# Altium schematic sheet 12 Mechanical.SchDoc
size 420 x 297 mm; DocumentNumber: 12; SheetNumber: 12; SheetTotal: 12
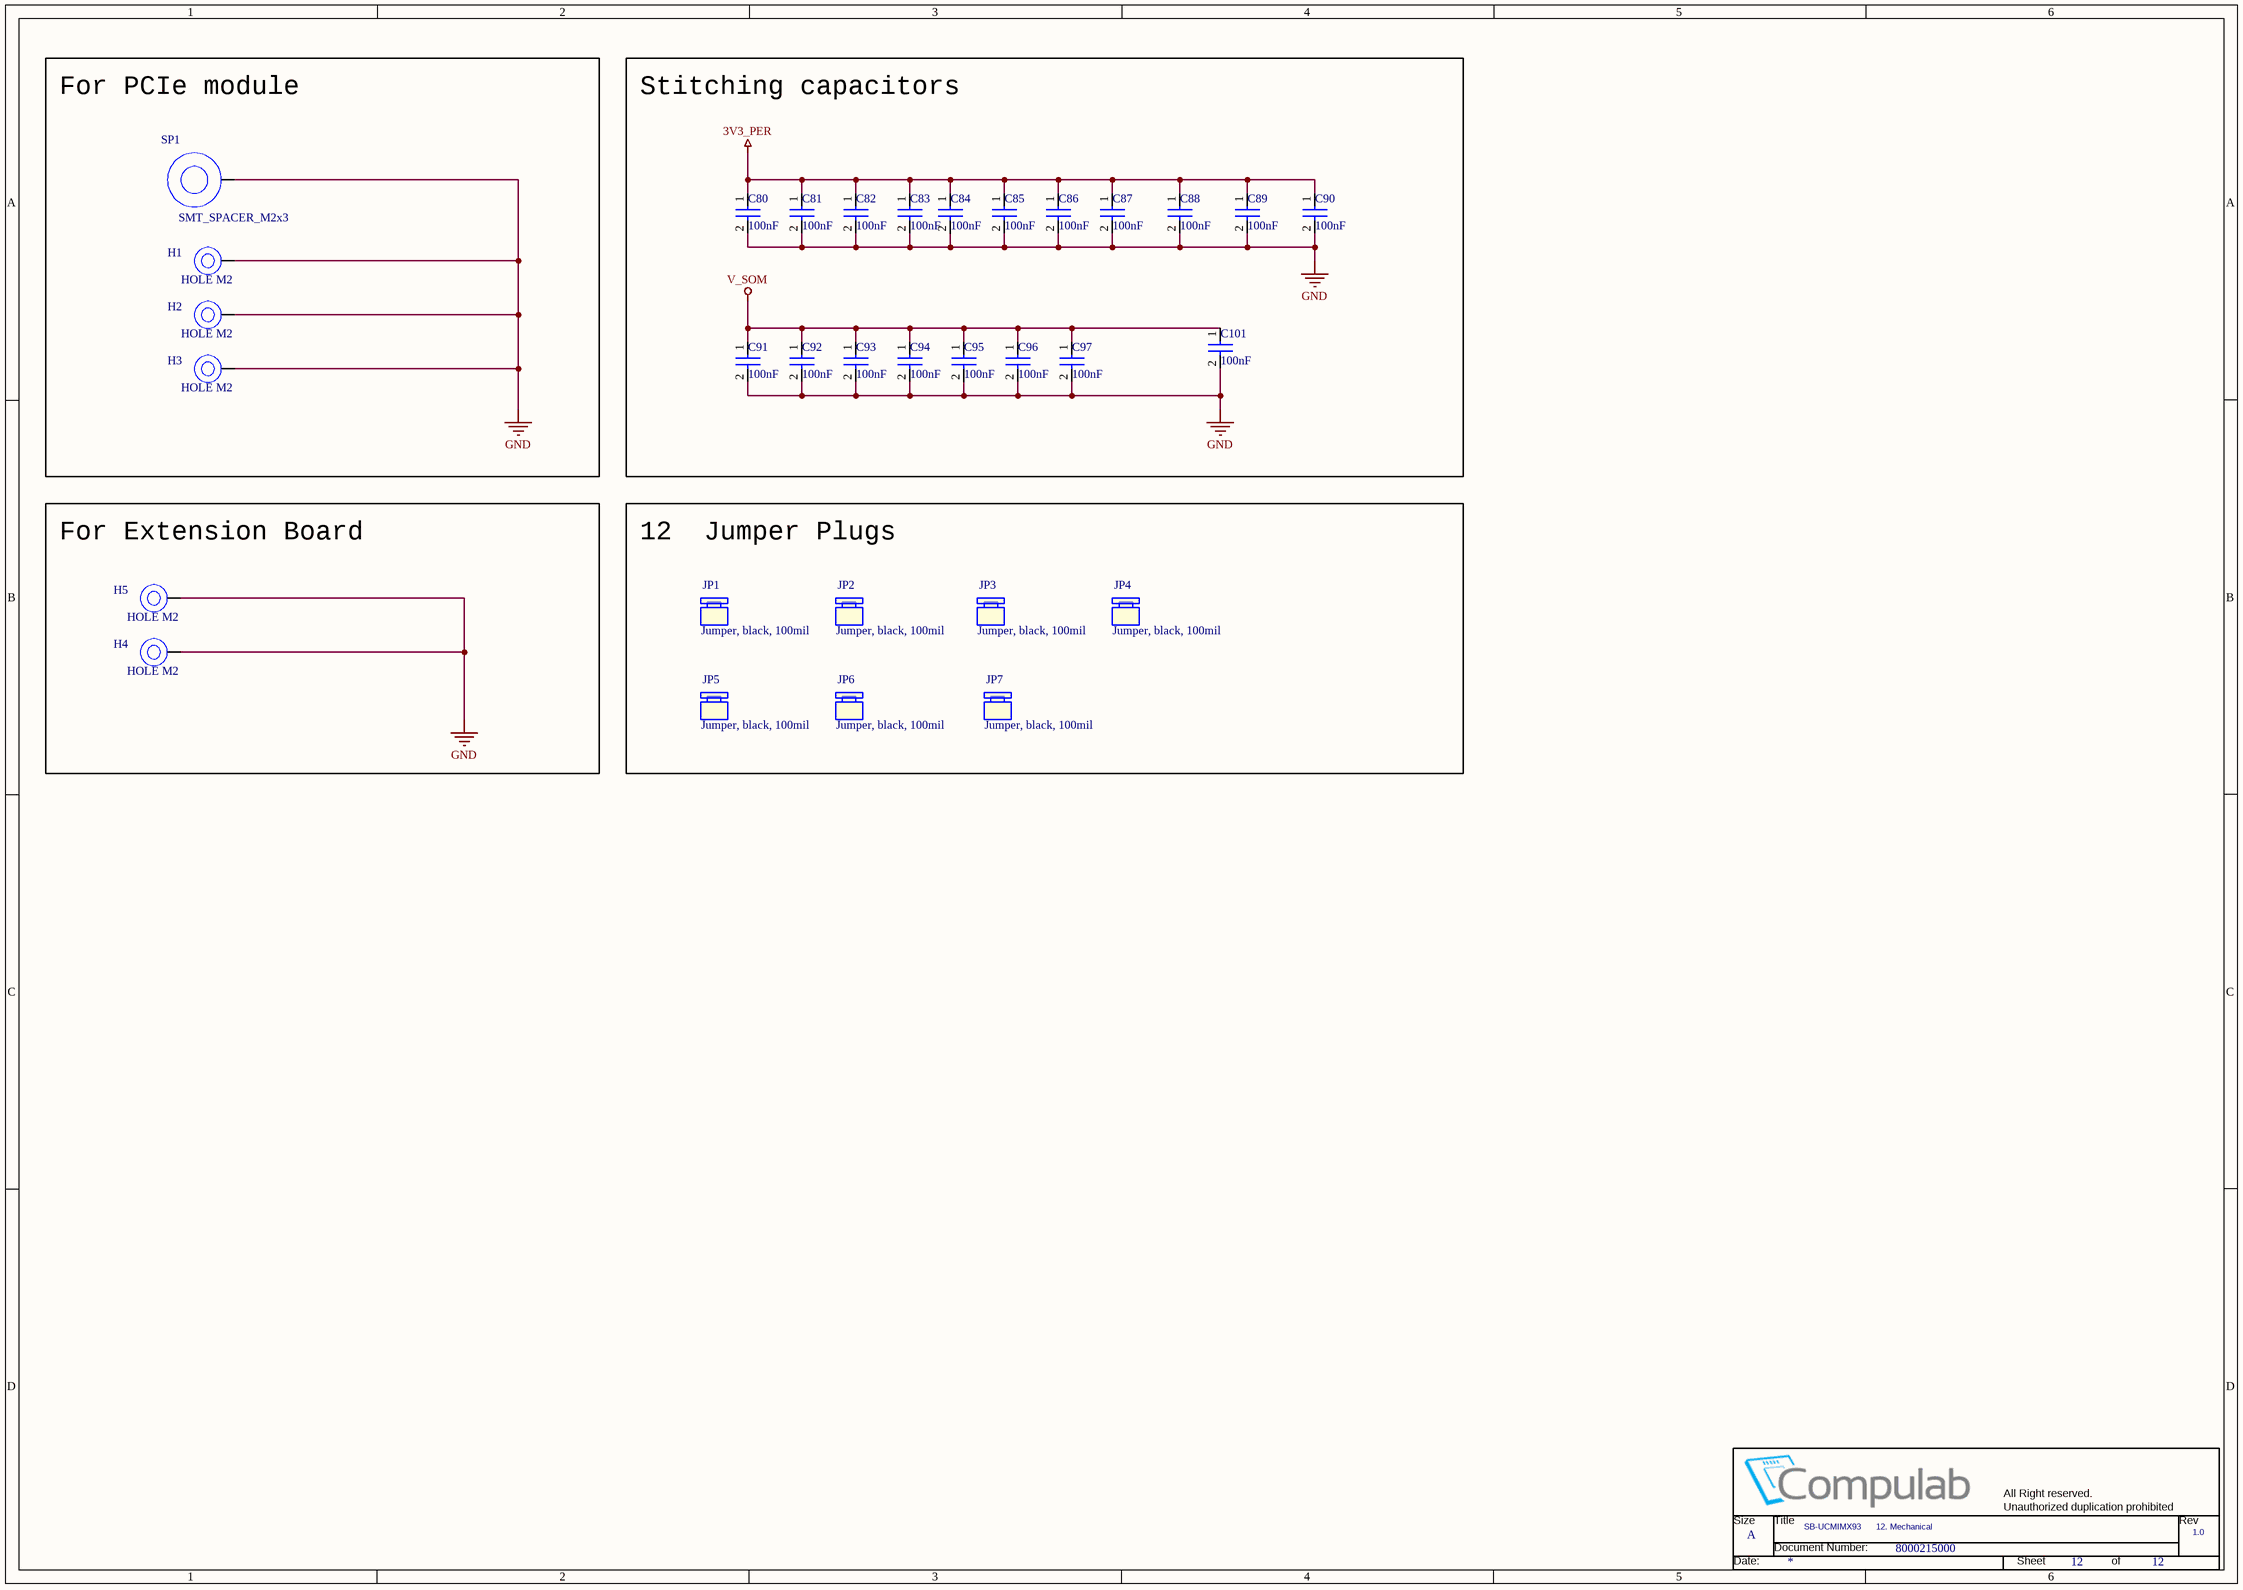
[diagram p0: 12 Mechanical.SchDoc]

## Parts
*  Title: SB-UCMIMX93      12. Mechanical  Doc: 8000215000  RevCode: 1.0  Page Size: A  Page Number: 12  (hidden comment: CompuLabTitleBlk)  (graphical)
C80  100nF  [RC0402]
C81  100nF  [RC0402]
C82  100nF  [RC0402]
C83  100nF  [RC0402]
C84  100nF  [RC0402]
C85  100nF  [RC0402]
C86  100nF  [RC0402]
C87  100nF  [RC0402]
C88  100nF  [RC0402]
C89  100nF  [RC0402]
C90  100nF  [RC0402]
C91  100nF  [RC0402]
C92  100nF  [RC0402]
C93  100nF  [RC0402]
C94  100nF  [RC0402]
C95  100nF  [RC0402]
C96  100nF  [RC0402]
C97  100nF  [RC0402]
C101  100nF  [RC0402]
H1  HOLE M2  [M2PAD]
H2  HOLE M2  [M2PAD]
H3  HOLE M2  [M2PAD]
H4  HOLE M2  [M2PAD]
H5  HOLE M2  [M2PAD]
JP1  Jumper, black, 100mil  [1X2THHDR]  (mechanical)
JP2  Jumper, black, 100mil  [2X5SMHDR]  (mechanical)
JP3  Jumper, black, 100mil  [2X5SMHDR]  (mechanical)
JP4  Jumper, black, 100mil  [2X17SMHDR]  (mechanical)
JP5  Jumper, black, 100mil  [21-0181B_T423590M-1_MXM]  (mechanical)
JP6  Jumper, black, 100mil  [0402]  (mechanical)
JP7  Jumper, black, 100mil  [0402]  (mechanical)
SP1  SMT_SPACER_M2x3  [MINIPCIE-4-Spacer]

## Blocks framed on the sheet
For PCIe module: H1-H3 SP1
Stitching capacitors: C80-C97 C101
For Extension Board: H4 H5
12  Jumper Plugs: JP1-JP7

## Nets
3V3_PER: C80.1 C81.1 C82.1 C83.1 C84.1 C85.1 C86.1 C87.1 C88.1 C89.1 C90.1
GND: C80.2 C81.2 C82.2 C83.2 C84.2 C85.2 C86.2 C87.2 C88.2 C89.2 C90.2 C91.2 C92.2 C93.2 C94.2 C95.2 C96.2 C97.2 C101.2 H1.1 H2.1 H3.1 H4.1 H5.1 SP1.NC
V_SOM: C91.1 C92.1 C93.1 C94.1 C95.1 C96.1 C97.1 C101.1

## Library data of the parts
C80-C97 C101 = 100nF, 10V, X7R, 10%, 0402_Dup1: P/N: 151B10400S
H1-H5 = Hole, Plated, M2, 5mm. ext.: P/N: 188Z10010; CLABCONF0: DNP
JP1-JP7 = Jumper, black, 100mil: P/N: 185B10010
SP1 = SMT_SPACER_M2x3_1: P/N: 383B52520S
